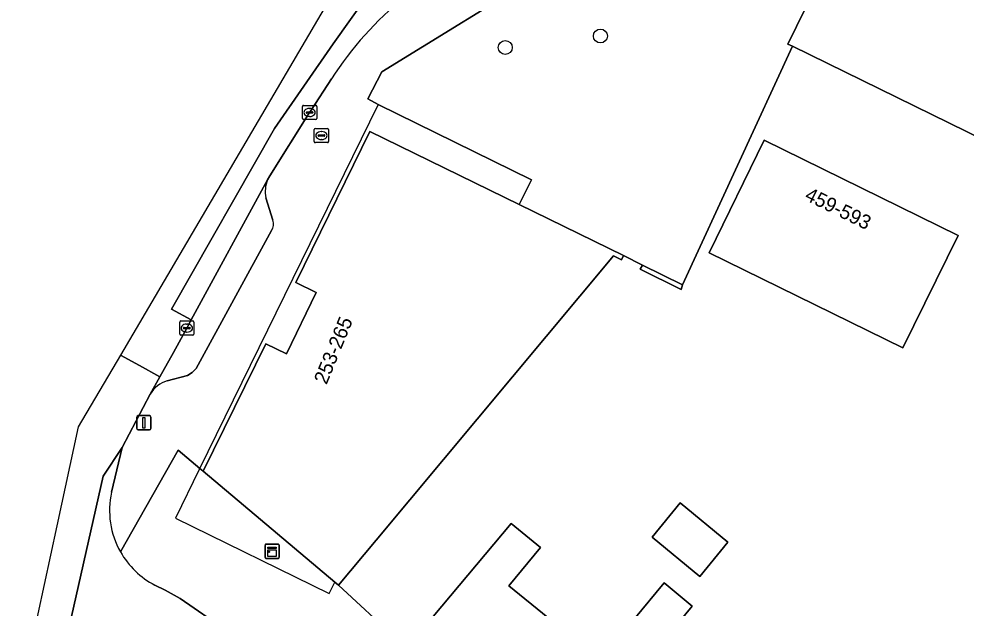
# Model space of a CAD drawing. Extents: x 160157 to 160921, y 381516 to 382045.
# Drawn here: x 160297.2 to 160363.6, y 381965.1 to 382006.4 of the extents above; entities that cross this region are included whole.
import ezdxf

# ---------------------------------------------------------------- set-up
doc = ezdxf.new("R2010")
doc.units = 0
for name, color, linetype in [('IMGEO_Boom', 7, 'Continuous'), ('IMGEO_Brandkraan', 7, 'Continuous'), ('IMGEO_Erf', 7, 'Continuous'), ('IMGEO_Groenvoorziening', 7, 'Continuous'), ('IMGEO_Kast', 7, 'Continuous'), ('IMGEO_Kolk', 7, 'Continuous'), ('IMGEO_Lichtmast', 7, 'Continuous'), ('IMGEO_Muur', 7, 'Continuous'), ('IMGEO_Pand', 7, 'Continuous'), ('IMGEO_Pand_nummerreeks', 7, 'Continuous'), ('IMGEO_Pand_overbouw', 7, 'Continuous'), ('IMGEO_Parkeervlak_open', 7, 'Continuous'), ('IMGEO_Rijbaan_lokaal_gesloten', 7, 'Continuous'), ('IMGEO_Rijbaan_lokaal_open', 7, 'Continuous'), ('IMGEO_Voetpad_open', 7, 'Continuous')]:
    doc.layers.add(name, color=color, linetype=linetype)

msp = doc.modelspace()

# ---------------------------------------------------------------- linework, layer by layer
at = {"layer": 'IMGEO_Boom'}
for centre in [(160337.967, 382005.204), (160331.292, 382004.402)]:
    msp.add_circle(centre, 0.489, dxfattribs=at)
at = {"layer": 'IMGEO_Brandkraan'}
for p, q in [((160317.966, 381998.723), (160318.818, 381998.723)), ((160317.891, 381997.797), (160317.891, 381998.649)), ((160318.15, 381998.217), (160318.15, 381998.229)), ((160318.588, 381998.18), (160318.19, 381998.18)), ((160318.193, 381998.266), (160318.591, 381998.266)), ((160318.379, 381998.503), (160318.404, 381998.503)), ((160318.634, 381998.229), (160318.634, 381998.217)), ((160318.892, 381998.649), (160318.892, 381997.797)), ((160318.818, 381997.723), (160317.966, 381997.723)), ((160318.402, 381997.943), (160318.377, 381997.943))]:
    msp.add_line(p, q, dxfattribs=at)
for points in [[(160317.966, 381998.723), (160318.818, 381998.723)], [(160317.891, 381997.797), (160317.891, 381998.649)], [(160318.892, 381998.649), (160318.892, 381997.797)], [(160318.818, 381997.723), (160317.966, 381997.723)]]:
    msp.add_lwpolyline(points, dxfattribs=at)
for centre, radius, start, end in [((160317.968, 381998.647), 0.0765, 91.55205, 178.44795), ((160317.968, 381998.647), 0.0765, 91.55205, 178.44795), ((160318.816, 381998.647), 0.0765, 1.55205, 88.44795), ((160318.816, 381998.647), 0.0765, 1.55205, 88.44795), ((160318.19, 381998.226), 0.0403, 85.87752, 175.75265), ((160318.187, 381998.216), 0.0366, 178.93798, 274.71019), ((160318.591, 381998.223), 0.043, 264.86636, 352.45326), ((160318.595, 381998.228), 0.0386, 1.73085, 96.63898), ((160317.968, 381997.799), 0.0765, 181.55205, 268.44795), ((160317.968, 381997.799), 0.0765, 181.55205, 268.44795), ((160318.816, 381997.799), 0.0765, 271.55205, 358.44795), ((160318.816, 381997.799), 0.0765, 271.55205, 358.44795)]:
    msp.add_arc(centre, radius, start, end, dxfattribs=at)
for centre, major_axis, ratio, start_param, end_param in [((160318.378, 381998.223), (-0.387, 0.002), 0.722429, 4.712389, 7.853982), ((160318.403, 381998.223), (-0.39, 0.002), 0.717154, 1.570796, 4.712389)]:
    msp.add_ellipse(centre, major_axis=major_axis, ratio=ratio, start_param=start_param, end_param=end_param, dxfattribs=at)
at = {"layer": 'IMGEO_Erf'}
for points in [[(160418.006, 381988.763), (160415.075, 381982.802), (160411.313, 381975.155), (160351.45, 382004.482), (160343.722, 381987.745), (160343.64, 381987.417), (160340.769, 381988.843), (160340.916, 381989.138), (160339.584, 381989.797), (160339.439, 381989.5), (160338.882, 381989.773), (160322.243, 381969.845), (160319.596, 381966.674), (160323.63, 381962.943)], [(160324.402, 381962.313), (160331.716, 381971.016), (160333.766, 381969.33), (160331.553, 381966.639), (160334.273, 381964.402)], [(160340.324, 381964.272), (160342.433, 381966.836), (160344.409, 381965.211), (160342.3, 381962.646)]]:
    msp.add_lwpolyline(points, dxfattribs=at)
for points in [[(160345.596, 381989.998), (160349.472, 381997.887), (160363.07, 381991.208), (160359.189, 381983.319)], [(160344.943, 381967.295), (160341.599, 381970.045), (160343.572, 381972.445), (160346.916, 381969.695)]]:
    msp.add_lwpolyline(points, close=True, dxfattribs=at)
at = {"layer": 'IMGEO_Groenvoorziening'}
msp.add_lwpolyline([(160346.599, 382017.482), (160334.359, 382009.925), (160322.638, 382002.688), (160321.642, 382000.798), (160322.378, 382000.41), (160333.132, 381995.12), (160332.263, 381993.378), (160339.584, 381989.797), (160340.916, 381989.138), (160343.722, 381987.745), (160351.45, 382004.482), (160351.126, 382004.641), (160354.769, 382012.086)], dxfattribs=at)
at = {"layer": 'IMGEO_Kast'}
for p, q in [((160314.431, 381968.628), (160314.431, 381969.469)), ((160314.431, 381969.469), (160314.431, 381968.628)), ((160314.506, 381969.553), (160315.347, 381969.553)), ((160315.347, 381969.553), (160314.506, 381969.553)), ((160315.431, 381969.478), (160315.431, 381968.637)), ((160315.431, 381968.637), (160315.431, 381969.478)), ((160315.356, 381968.553), (160314.515, 381968.553)), ((160314.515, 381968.553), (160315.356, 381968.553))]:
    msp.add_line(p, q, dxfattribs=at)
for points in [[(160314.626, 381969.343), (160315.226, 381969.343), (160315.226, 381969.258), (160314.626, 381969.258), (160314.626, 381969.343)], [(160314.626, 381969.168), (160315.226, 381969.168), (160315.226, 381968.679), (160314.626, 381968.679), (160314.626, 381969.168)]]:
    msp.add_lwpolyline(points, dxfattribs=at)
msp.add_circle((160314.71, 381969.017), 0.0377, dxfattribs=at)
for centre, start, end in [((160314.509, 381969.475), 92.4484, 184.28452), ((160314.509, 381969.475), 92.4484, 184.28452), ((160315.353, 381969.475), 2.4484, 94.28452), ((160315.353, 381969.475), 2.4484, 94.28452), ((160314.509, 381968.631), 182.4484, 274.28452), ((160314.509, 381968.631), 182.4484, 274.28452), ((160315.353, 381968.631), 272.4484, 4.28452), ((160315.353, 381968.631), 272.4484, 4.28452)]:
    msp.add_arc(centre, 0.0779, start, end, dxfattribs=at)
at = {"layer": 'IMGEO_Kolk'}
for p, q in [((160317.059, 381999.414), (160317.059, 382000.266)), ((160317.134, 382000.34), (160317.986, 382000.34)), ((160317.547, 382000.12), (160317.572, 382000.12)), ((160318.06, 382000.266), (160318.06, 381999.414)), ((160317.318, 381999.834), (160317.318, 381999.846)), ((160317.756, 381999.797), (160317.358, 381999.797)), ((160317.361, 381999.883), (160317.759, 381999.883)), ((160317.57, 381999.56), (160317.545, 381999.56)), ((160317.802, 381999.846), (160317.802, 381999.834)), ((160317.986, 381999.34), (160317.134, 381999.34)), ((160308.445, 381984.289), (160308.445, 381985.141)), ((160308.52, 381985.215), (160309.372, 381985.215)), ((160308.747, 381984.758), (160309.145, 381984.758)), ((160308.933, 381984.995), (160308.958, 381984.995)), ((160309.446, 381985.141), (160309.446, 381984.289)), ((160309.372, 381984.215), (160308.52, 381984.215)), ((160308.704, 381984.709), (160308.704, 381984.721)), ((160309.142, 381984.672), (160308.744, 381984.672)), ((160308.956, 381984.435), (160308.931, 381984.435)), ((160309.188, 381984.721), (160309.188, 381984.709))]:
    msp.add_line(p, q, dxfattribs=at)
for points in [[(160317.059, 381999.414), (160317.059, 382000.266)], [(160317.134, 382000.34), (160317.986, 382000.34)], [(160318.06, 382000.266), (160318.06, 381999.414)], [(160317.986, 381999.34), (160317.134, 381999.34)], [(160308.445, 381984.289), (160308.445, 381985.141)], [(160308.52, 381985.215), (160309.372, 381985.215)], [(160309.446, 381985.141), (160309.446, 381984.289)], [(160309.372, 381984.215), (160308.52, 381984.215)]]:
    msp.add_lwpolyline(points, dxfattribs=at)
for centre, radius, start, end in [((160317.136, 382000.264), 0.0765, 91.55205, 178.44795), ((160317.136, 382000.264), 0.0765, 91.55205, 178.44795), ((160317.984, 382000.264), 0.0765, 1.55205, 88.44795), ((160317.984, 382000.264), 0.0765, 1.55205, 88.44795), ((160317.136, 381999.416), 0.0765, 181.55205, 268.44795), ((160317.136, 381999.416), 0.0765, 181.55205, 268.44795), ((160317.358, 381999.843), 0.0403, 85.87752, 175.75265), ((160317.355, 381999.833), 0.0366, 178.93798, 274.71019), ((160317.759, 381999.84), 0.043, 264.86636, 352.45326), ((160317.763, 381999.845), 0.0386, 1.73085, 96.63898), ((160317.984, 381999.416), 0.0765, 271.55205, 358.44795), ((160317.984, 381999.416), 0.0765, 271.55205, 358.44795), ((160308.522, 381985.139), 0.0765, 91.55205, 178.44795), ((160308.522, 381985.139), 0.0765, 91.55205, 178.44795), ((160308.744, 381984.718), 0.0403, 85.87752, 175.75265), ((160309.149, 381984.72), 0.0386, 1.73085, 96.63898), ((160309.37, 381985.139), 0.0765, 1.55205, 88.44795), ((160309.37, 381985.139), 0.0765, 1.55205, 88.44795), ((160308.522, 381984.291), 0.0765, 181.55205, 268.44795), ((160308.522, 381984.291), 0.0765, 181.55205, 268.44795), ((160308.741, 381984.708), 0.0366, 178.93798, 274.71019), ((160309.145, 381984.715), 0.043, 264.86636, 352.45326), ((160309.37, 381984.291), 0.0765, 271.55205, 358.44795), ((160309.37, 381984.291), 0.0765, 271.55205, 358.44795)]:
    msp.add_arc(centre, radius, start, end, dxfattribs=at)
for centre, major_axis, ratio, start_param, end_param in [((160317.546, 381999.84), (-0.387, 0.002), 0.722429, 4.712389, 7.853982), ((160317.571, 381999.84), (-0.39, 0.002), 0.717154, 1.570796, 4.712389), ((160308.932, 381984.715), (-0.387, 0.002), 0.722429, 4.712389, 7.853982), ((160308.957, 381984.715), (-0.39, 0.002), 0.717154, 1.570796, 4.712389)]:
    msp.add_ellipse(centre, major_axis=major_axis, ratio=ratio, start_param=start_param, end_param=end_param, dxfattribs=at)
at = {"layer": 'IMGEO_Lichtmast'}
for p, q in [((160305.439, 381977.671), (160305.439, 381978.471)), ((160305.439, 381978.471), (160305.439, 381977.671)), ((160305.539, 381978.571), (160306.329, 381978.571)), ((160306.329, 381978.571), (160305.539, 381978.571)), ((160306.429, 381978.471), (160306.429, 381977.671)), ((160306.429, 381977.671), (160306.429, 381978.471)), ((160306.329, 381977.571), (160305.539, 381977.571)), ((160305.539, 381977.571), (160306.329, 381977.571))]:
    msp.add_line(p, q, dxfattribs=at)
msp.add_lwpolyline([(160305.859, 381978.446), (160306.009, 381978.446), (160306.009, 381977.696), (160305.859, 381977.696), (160305.859, 381978.446)], dxfattribs=at)
for centre, start, end in [((160305.539, 381978.471), 90, 180), ((160305.539, 381978.471), 90, 180), ((160306.329, 381978.471), 0, 90), ((160306.329, 381978.471), 360, 90), ((160305.539, 381977.671), 180, 270), ((160305.539, 381977.671), 180, 270), ((160306.329, 381977.671), 270, 0), ((160306.329, 381977.671), 270, 0)]:
    msp.add_arc(centre, 0.1, start, end, dxfattribs=at)
at = {"layer": 'IMGEO_Muur'}
msp.add_lwpolyline([(160340.916, 381989.138), (160340.769, 381988.843), (160343.64, 381987.417), (160343.722, 381987.745)], close=True, dxfattribs=at)
at = {"layer": 'IMGEO_Pand'}
msp.add_lwpolyline([(160373.026, 382011.418), (160358.403, 382018.579), (160358.163, 382018.089), (160359.146, 382017.608), (160358.953, 382017.212), (160356.127, 382011.423), (160354.925, 382012.01), (160354.769, 382012.086), (160351.126, 382004.641), (160351.45, 382004.482), (160411.313, 381975.155)], dxfattribs=at)
for points in [[(160310.098, 381974.666), (160319.323, 381966.9), (160319.596, 381966.674), (160322.243, 381969.845), (160338.882, 381989.773), (160339.439, 381989.5), (160339.584, 381989.797), (160332.263, 381993.378), (160321.788, 381998.503), (160316.6, 381987.908), (160318.028, 381987.209), (160315.929, 381982.908), (160314.492, 381983.613)], [(160363.07, 381991.208), (160349.472, 381997.887), (160345.596, 381989.998), (160359.189, 381983.319)], [(160344.943, 381967.295), (160346.916, 381969.695), (160343.572, 381972.445), (160341.599, 381970.045)], [(160334.273, 381964.402), (160331.553, 381966.639), (160333.766, 381969.33), (160331.716, 381971.016), (160324.402, 381962.313), (160329.267, 381958.313)], [(160340.324, 381964.272), (160342.3, 381962.646), (160344.409, 381965.211), (160342.433, 381966.836)]]:
    msp.add_lwpolyline(points, close=True, dxfattribs=at)
at = {"layer": 'IMGEO_Pand_overbouw'}
msp.add_lwpolyline([(160319.323, 381966.9), (160310.098, 381974.666), (160314.492, 381983.613), (160315.929, 381982.908), (160318.028, 381987.209), (160316.6, 381987.908), (160321.788, 381998.503), (160332.263, 381993.378), (160333.132, 381995.12), (160322.378, 382000.41), (160309.82, 381974.797), (160308.142, 381971.374), (160318.934, 381966.095)], close=True, dxfattribs=at)
at = {"layer": 'IMGEO_Parkeervlak_open'}
for points in [[(160314.618, 381995.117), (160309.257, 381985.294), (160308.941, 381984.715), (160308.001, 381983.009), (160307.059, 381981.3), (160306.384, 381980.075)], [(160314.972, 381992.287), (160314.499, 381993.855)], [(160307.575, 381981.017), (160308.994, 381981.381), (160309.319, 381981.61), (160309.594, 381981.889), (160314.889, 381991.559)]]:
    msp.add_lwpolyline(points, dxfattribs=at)
for centre, radius, start, end in [((160316.43, 381994.31), 1.984, 155.97923, 193.24724), ((160314.199, 381992.006), 0.823, 327.05009, 19.94138), ((160308.132, 381979.089), 2.007, 106.11408, 150.56912)]:
    msp.add_arc(centre, radius, start, end, dxfattribs=at)
at = {"layer": 'IMGEO_Rijbaan_lokaal_gesloten'}
for points in [[(160344.08, 382033.65), (160340.582, 382035.682), (160325.572, 382019.052), (160304.281, 381982.823)], [(160304.281, 381982.823), (160304.281, 381982.823), (160305.62, 381982.089), (160307.059, 381981.3), (160308.001, 381983.009), (160308.941, 381984.715), (160309.257, 381985.294), (160307.875, 381986.048), (160315.098, 381998.726), (160319.223, 382004.666), (160321.761, 382008.248), (160325.721, 382013.341)], [(160297.164, 381958.502), (160297.164, 381958.502), (160298.281, 381958.318), (160299.617, 381958.101), (160299.638, 381958.223), (160300.303, 381962.088), (160303.083, 381974.326), (160304.41, 381976.336), (160306.384, 381980.075), (160307.059, 381981.3), (160305.62, 381982.089), (160304.281, 381982.823), (160304.281, 381982.823), (160301.32, 381977.785), (160299.825, 381970.848), (160297.164, 381958.502)]]:
    msp.add_lwpolyline(points, dxfattribs=at)
at = {"layer": 'IMGEO_Rijbaan_lokaal_open'}
for points in [[(160325.721, 382013.341), (160321.761, 382008.248), (160319.223, 382004.666), (160315.098, 381998.726), (160307.875, 381986.048), (160309.257, 381985.294), (160314.618, 381995.117)], [(160314.618, 381995.117), (160314.769, 381995.393), (160317.56, 381999.84), (160317.664, 382000), (160319.095, 382002.191)], [(160303.659, 381973.194), (160304.41, 381976.336), (160303.083, 381974.326), (160300.303, 381962.088), (160299.638, 381958.223)], [(160308.469, 381965.745), (160307.425, 381966.322), (160306.699, 381966.686)], [(160308.058, 381959.424), (160309.064, 381958.612), (160312.536, 381962.804), (160311.735, 381963.499), (160308.469, 381965.745)]]:
    msp.add_lwpolyline(points, dxfattribs=at)
for centre, radius, start, end in [((160338.789, 381989.672), 23.336, 128.58774, 147.55744), ((160309.418, 381971.926), 5.897, 167.58076, 209.588), ((160309.411, 381971.903), 5.88, 209.42859, 242.53067)]:
    msp.add_arc(centre, radius, start, end, dxfattribs=at)
at = {"layer": 'IMGEO_Voetpad_open'}
for points in [[(160304.29, 381969.014), (160308.327, 381976.157), (160309.856, 381974.87), (160310.098, 381974.666), (160314.492, 381983.613), (160315.929, 381982.908), (160318.028, 381987.209), (160316.6, 381987.908), (160321.788, 381998.503), (160332.263, 381993.378), (160333.132, 381995.12), (160322.378, 382000.41), (160321.642, 382000.798), (160322.638, 382002.688), (160334.359, 382009.925), (160346.599, 382017.482)], [(160319.095, 382002.191), (160317.664, 382000), (160317.56, 381999.84), (160314.769, 381995.393), (160314.618, 381995.117)], [(160314.499, 381993.855), (160314.972, 381992.287)], [(160314.889, 381991.559), (160309.594, 381981.889), (160309.319, 381981.61), (160308.994, 381981.381), (160307.575, 381981.017)], [(160306.384, 381980.075), (160304.41, 381976.336), (160303.659, 381973.194)], [(160323.63, 381962.943), (160319.596, 381966.674), (160319.323, 381966.9), (160310.098, 381974.666), (160309.856, 381974.87), (160308.327, 381976.157), (160304.29, 381969.014)], [(160306.699, 381966.686), (160307.425, 381966.322), (160308.469, 381965.745), (160311.735, 381963.499)]]:
    msp.add_lwpolyline(points, dxfattribs=at)
for centre, radius, start, end in [((160338.789, 381989.672), 23.336, 128.58774, 147.55744), ((160316.43, 381994.31), 1.984, 155.97923, 193.24724), ((160314.199, 381992.006), 0.823, 327.05009, 19.94138), ((160308.132, 381979.089), 2.007, 106.11408, 150.56912), ((160309.418, 381971.926), 5.897, 167.58076, 209.588), ((160309.411, 381971.903), 5.88, 209.42859, 242.53067)]:
    msp.add_arc(centre, radius, start, end, dxfattribs=at)

# ---------------------------------------------------------------- texts
at = {"layer": 'IMGEO_Pand_nummerreeks'}
for s, rotation, p in [('459-593', 333.83875, (160352.239, 381993.743)), ('253-265', 67.71263, (160318.75, 381980.704))]:
    msp.add_text(s, height=1, rotation=rotation, dxfattribs=at).set_placement(p)

doc.saveas('drawing.dxf')
